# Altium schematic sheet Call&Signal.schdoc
size 192 x 157 mm
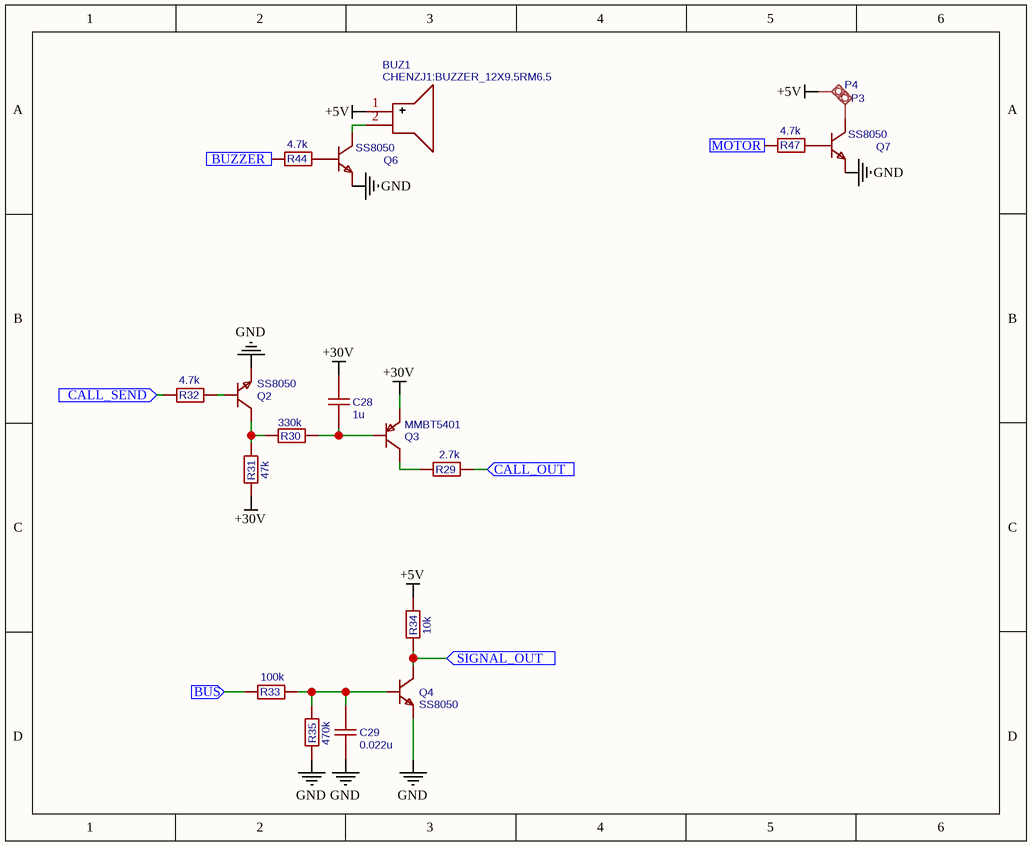
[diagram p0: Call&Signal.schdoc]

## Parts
BUZ1  CHENZJ1:BUZZER_12X9.5RM6.5  [BUZ-TH_BD12.0-P6.50-D0.6_SEA-1285F]
C28  1u  [C1206]
C29  0.022u  [C0805]
P3  TESTPAD50  [TESTPAD-50-ROUND]  (value not drawn)
P4  TESTPAD50  [TESTPAD-50-ROUND]  (value not drawn)
Q2  SS8050  [SOT-23-3_L2.9-W1.3-P1.90-LS2.4-BR]
Q3  MMBT5401  [SOT-23-3_L2.9-W1.3-P1.90-LS2.4-BR]
Q4  SS8050  [SOT-23-3_L2.9-W1.3-P1.90-LS2.4-BR]
Q6  SS8050  [SOT-23-3_L2.9-W1.3-P1.90-LS2.4-BR]
Q7  SS8050  [SOT-23-3_L2.9-W1.3-P1.90-LS2.4-BR]
R29  2.7k  [R0805]
R30  330k  [R0805]
R31  47k  [R0805]
R32  4.7k  [R1206]
R33  100k  [R1206]
R34  10k  [R1206]
R35  470k  [R0805]
R44  4.7k  [R1206]
R47  4.7k  [R1206]

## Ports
BUS (in), BUZZER (in), CALL_OUT (in), CALL_SEND (in), MOTOR (in), SIGNAL_OUT (in)

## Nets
+5V: BUZ1.1(+) P4.1(PP) R34.2
+30V: C28.2 Q3.2(E) R31.1
GND: C29.1 Q2.2(E) Q4.2(E) Q6.2(E) Q7.2(E) R35.1
BUS: R33.2 ; port BUS
BUZZER: R44.2 ; port BUZZER
CALL_OUT: R29.2 ; port CALL_OUT
CALL_SEND: R32.2 ; port CALL_SEND
MOTOR: R47.2 ; port MOTOR
SIGNAL_OUT: Q4.3(C) R34.1 ; port SIGNAL_OUT
NetBUZ1_2: BUZ1.2(-) Q6.3(C)
NetC28_1: C28.1 Q3.1(B) R30.2
NetC29_2: C29.2 Q4.1(B) R33.1 R35.2
NetP3_1: P3.1(PP) Q7.3(C)
NetQ2_1: Q2.1(B) R32.1
NetQ2_3: Q2.3(C) R30.1 R31.2
NetQ3_3: Q3.3(C) R29.1
NetQ6_1: Q6.1(B) R44.1
NetQ7_1: Q7.1(B) R47.1

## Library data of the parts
BUZ1 = CHENZJ1:BUZZER_12X9.5RM6.5: BOM_Manufacturer: null; Contributor: LCSC
C28 = 1u: BOM_Manufacturer Part: CL31B105KBHNNNE; BOM_Manufacturer: SAMSUNG(三星); nameAlias: Value(F); Contributor: LCEDA_Lib
C29 = 0.022u: BOM_Manufacturer Part: CL21B223KBANNNC; BOM_Manufacturer: SAMSUNG(三星); nameAlias: Value(F); Contributor: LCEDA_Lib
P3 P4 = TESTPAD50: Contributor: radiofm
Q2 Q4 Q6 Q7 = SS8050: BOM_Manufacturer: CJ(江苏长电/长晶)
Q3 = MMBT5401: BOM_Manufacturer: CJ(江苏长电/长晶); Contributor: 立创EDA官方封装库
R29 = 2.7k: BOM_Manufacturer Part: 0805W8F2701T5E; nameAlias: Value(Ω); Contributor: LCEDA_Lib
R30 = 330k: BOM_Manufacturer Part: 0805W8F3303T5E; BOM_Manufacturer: UNI-ROYAL(厚声); nameAlias: Value(Ω); Contributor: LCEDA_Lib
R31 = 47k: BOM_Manufacturer Part: 0805W8F4702T5E; BOM_Manufacturer: UNI-ROYAL(厚声); nameAlias: Value(Ω); Contributor: LCEDA_Lib
R32 R44 R47 = 4.7k: BOM_Manufacturer Part: 1206W4F4701T5E; BOM_Manufacturer: UNI-ROYAL(厚声); nameAlias: Value(Ω); Contributor: LCEDA_Lib
R33 = 100k: BOM_Manufacturer Part: 1206W4F1003T5E; BOM_Manufacturer: UNI-ROYAL(厚声); nameAlias: Value(Ω); Contributor: LCEDA_Lib
R34 = 10k: BOM_Manufacturer Part: 1206W4F1002T5E; BOM_Manufacturer: UNI-ROYAL(厚声); nameAlias: Value(Ω); Contributor: LCEDA_Lib
R35 = 470k: BOM_Manufacturer Part: 0805W8F4703T5E; BOM_Manufacturer: UNI-ROYAL(厚声); nameAlias: Value(Ω); Contributor: LCEDA_Lib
